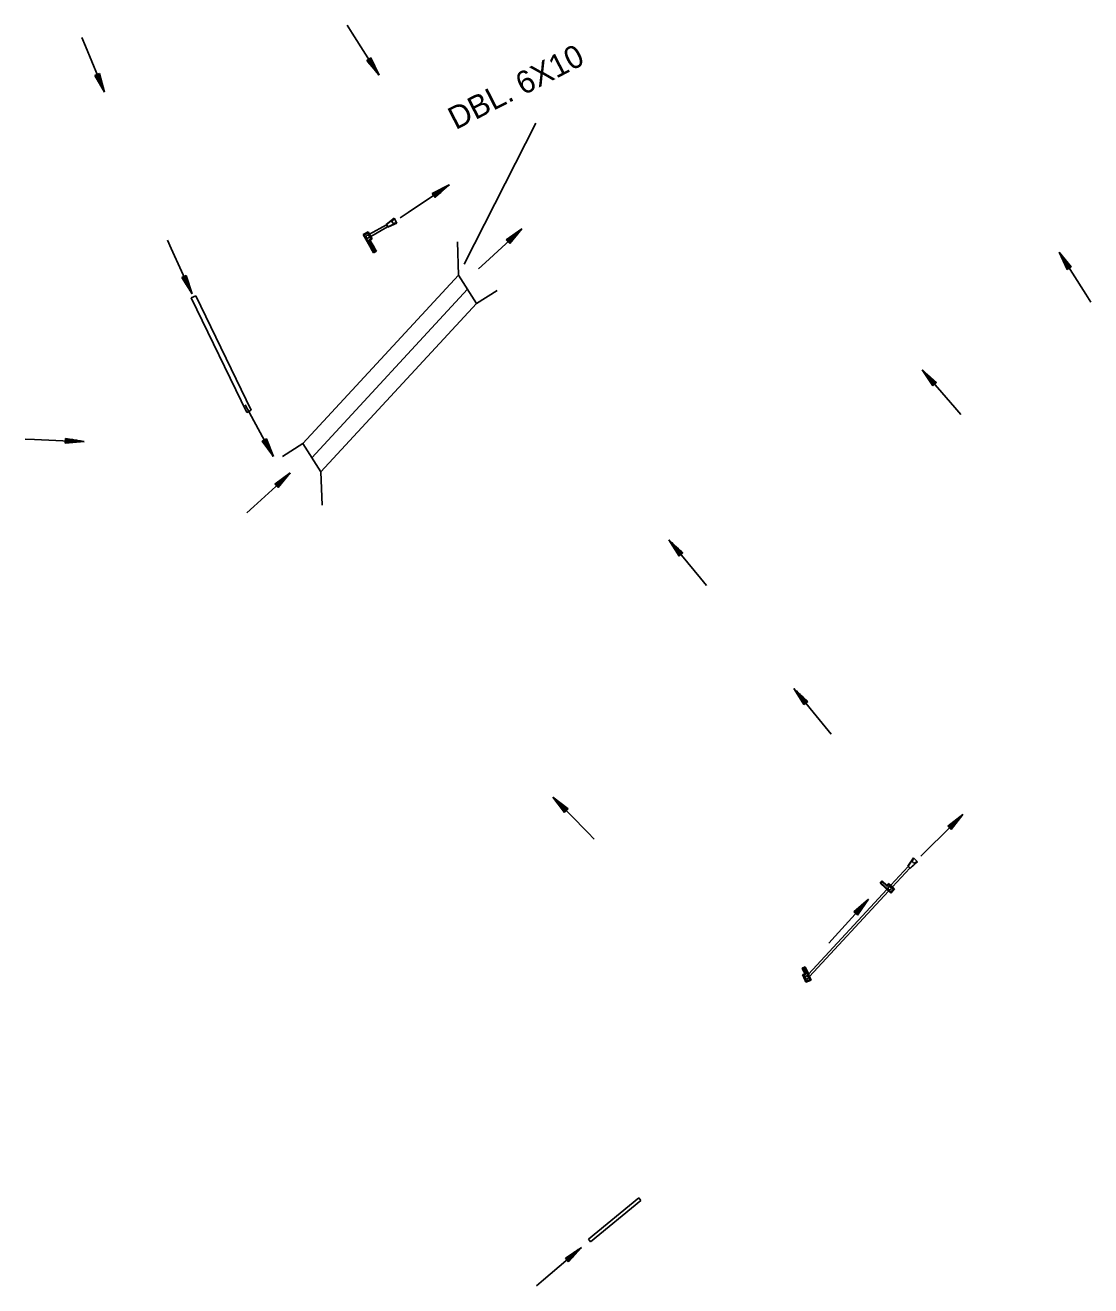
# Model space of a CAD drawing. Extents: x 1308292 to 1312792, y 238563 to 242743.
# Drawn here: x 1312134 to 1312792, y 238563 to 239341 of the extents above; entities that cross this region are included whole.
import ezdxf

# ---------------------------------------------------------------- set-up
doc = ezdxf.new("R2010")
doc.units = 0
for name, color, linetype in [('R_Box Culvert', 7, 'Continuous'), ('R_BRIDGE OLD', 7, 'Continuous'), ('R_Drop Inlet', 7, 'Continuous'), ('R_FES', 7, 'Continuous'), ('R_Flow Arrows', 7, 'Continuous'), ('R_Pipe Culvert', 7, 'Continuous')]:
    doc.layers.add(name, color=color, linetype=linetype)

msp = doc.modelspace()

# ---------------------------------------------------------------- linework, layer by layer
at = {"layer": 'R_Box Culvert'}
for p, q in [((1312401.3, 239187), (1312400.49, 239207.48)), ((1312305.15, 239082.96), (1312401.3, 239187)), ((1312401.3, 239187), (1312412.35, 239169.49)), ((1312310.68, 239074.2), (1312406.82, 239178.24)), ((1312412.35, 239169.49), (1312425.03, 239177.49)), ((1312316.21, 239065.45), (1312412.35, 239169.49)), ((1312292.47, 239074.95), (1312305.15, 239082.96)), ((1312305.15, 239082.96), (1312316.21, 239065.45)), ((1312317.01, 239044.96), (1312316.21, 239065.45))]:
    msp.add_line(p, q, dxfattribs=at)
at = {"layer": 'R_BRIDGE OLD'}
msp.add_line((1312404.65, 239193.81), (1312449.03, 239280.73), dxfattribs=at)
at = {"layer": 'R_Drop Inlet'}
for p, q in [((1312345.43, 239213.74), (1312342.38, 239212.02)), ((1312345.24, 239213.06), (1312343.06, 239211.83)), ((1312347.2, 239209.57), (1312345.9, 239208.84)), ((1312347.89, 239209.39), (1312346.58, 239208.65)), ((1312350.54, 239201.7), (1312348.8, 239200.72)), ((1312349.86, 239201.89), (1312348.99, 239201.4)), ((1312661.44, 238811.39), (1312662.74, 238812.91)), ((1312662.74, 238812.91), (1312665.69, 238810.21)), ((1312661.44, 238811.39), (1312668.08, 238805.31)), ((1312662.13, 238811.43), (1312662.78, 238812.19)), ((1312662.13, 238811.43), (1312668.04, 238806.03)), ((1312662.78, 238812.19), (1312665.74, 238809.49)), ((1312665.69, 238810.21), (1312666.67, 238811.35)), ((1312665.74, 238809.49), (1312666.71, 238810.63)), ((1312666.67, 238811.35), (1312668.1, 238810.04)), ((1312666.71, 238810.63), (1312667.76, 238809.67)), ((1312668.04, 238806.03), (1312669.69, 238807.96)), ((1312668.08, 238805.31), (1312670.39, 238808.01)), ((1312615.15, 238759.74), (1312613.27, 238759.01)), ((1312614.91, 238759.11), (1312613.97, 238758.75)), ((1312615.05, 238755.41), (1312613.65, 238754.87)), ((1312615.72, 238755.14), (1312614.32, 238754.59)), ((1312618.87, 238751.53), (1312615.61, 238750.26)), ((1312618.22, 238751.81), (1312615.89, 238750.91))]:
    msp.add_line(p, q, dxfattribs=at)
for centre in [(1312345.13, 239210.7), (1312667.38, 238808.33), (1312616.3, 238753.21)]:
    msp.add_circle(centre, 1, dxfattribs=at)
for centre, radius, start, end in [((1313743.71, 240000.7), 1608.02, 209.37112, 209.83433), ((1313743.71, 240000.7), 1607.52, 209.38892, 209.81663), ((1313743.71, 240000.7), 1605.02, 209.38887, 209.53166), ((1313743.71, 240000.7), 1604.52, 209.371, 209.54955), ((1313743.71, 240000.7), 1606.52, 209.53156, 209.81688), ((1313743.71, 240000.7), 1606.02, 209.54943, 209.83484), ((1312730.28, 238878), 92.61, 227.54111, 229.13681), ((1312730.28, 238878), 92.11, 227.54111, 229.44615), ((1312438.08, 238668.91), 197, 26.78536, 27.21582), ((1312438.08, 238668.91), 197.5, 26.78536, 27.05463), ((1312545.2, 238722.99), 77.5, 24.50372, 26.78543), ((1312438.08, 238668.91), 198.5, 26.78536, 27.02491), ((1312438.08, 238668.91), 199, 26.78535, 27.15489), ((1312545.2, 238722.99), 78.5, 21.53994, 26.78543), ((1312545.2, 238722.99), 79, 21.17499, 26.78543), ((1312545.2, 238722.99), 75.5, 21.17499, 24.9722), ((1312545.2, 238722.99), 77, 24.89812, 26.78543), ((1312545.2, 238722.99), 76, 21.55194, 24.56949)]:
    msp.add_arc(centre, radius, start, end, dxfattribs=at)
at = {"layer": 'R_FES'}
for p, q in [((1312356.58, 239218.27), (1312361.39, 239222.13)), ((1312356.58, 239218.27), (1312357.52, 239216.6)), ((1312356.82, 239218.19), (1312356.58, 239218.27)), ((1312356.82, 239218.19), (1312361.49, 239221.94)), ((1312356.82, 239218.19), (1312357.57, 239216.85)), ((1312357.52, 239216.6), (1312363.11, 239219.08)), ((1312357.57, 239216.85), (1312363.01, 239219.26)), ((1312360.36, 239220.53), (1312361.39, 239222.13)), ((1312361.49, 239221.94), (1312360.36, 239220.53)), ((1312361.32, 239218.96), (1312363.01, 239219.26)), ((1312363.11, 239219.08), (1312361.32, 239218.96)), ((1312361.39, 239222.13), (1312363.11, 239219.08)), ((1312357.57, 239216.85), (1312357.52, 239216.6)), ((1312678.6, 238821.86), (1312681.98, 238827.02)), ((1312678.6, 238821.86), (1312680.02, 238820.56)), ((1312678.85, 238821.86), (1312678.6, 238821.86)), ((1312678.85, 238821.86), (1312682.13, 238826.87)), ((1312678.85, 238821.86), (1312679.99, 238820.82)), ((1312679.99, 238820.82), (1312684.41, 238824.79)), ((1312679.99, 238820.82), (1312680.02, 238820.56)), ((1312680.02, 238820.56), (1312684.56, 238824.65)), ((1312681.5, 238825.18), (1312681.98, 238827.02)), ((1312682.13, 238826.87), (1312681.5, 238825.18)), ((1312681.98, 238827.02), (1312684.56, 238824.65)), ((1312682.9, 238823.99), (1312684.41, 238824.79)), ((1312684.56, 238824.65), (1312682.9, 238823.99))]:
    msp.add_line(p, q, dxfattribs=at)
for centre, start, end in [((1312361.18, 239219.95), 144.64995, 278.18069), ((1312682.45, 238824.88), 162.7308, 296.26153)]:
    msp.add_arc(centre, 1, start, end, dxfattribs=at)
at = {"layer": 'R_Flow Arrows'}
for p, q in [((1312344.52, 239319.57), (1312347.07, 239321.22)), ((1312344.52, 239319.57), (1312352.17, 239310.53)), ((1312347.07, 239321.22), (1312352.17, 239310.53)), ((1312179.6, 239311.45), (1312176.79, 239310.29)), ((1312179.6, 239311.45), (1312182.68, 239300.01)), ((1312176.79, 239310.29), (1312182.68, 239300.01)), ((1312384.98, 239237.42), (1312395.54, 239242.79)), ((1312386.7, 239234.9), (1312395.54, 239242.79)), ((1312384.98, 239237.42), (1312386.7, 239234.9)), ((1312430.73, 239208.69), (1312440.35, 239215.61)), ((1312432.81, 239206.47), (1312440.35, 239215.61)), ((1312430.73, 239208.69), (1312432.81, 239206.47)), ((1312779.5, 239192.01), (1312771.92, 239201.11)), ((1312776.94, 239190.38), (1312771.92, 239201.11)), ((1312233.13, 239186.73), (1312230.38, 239185.45)), ((1312233.13, 239186.73), (1312236.71, 239175.44)), ((1312776.94, 239190.38), (1312779.5, 239192.01)), ((1312230.38, 239185.45), (1312236.71, 239175.44)), ((1312696.22, 239120.6), (1312687.36, 239128.47)), ((1312693.92, 239118.6), (1312687.36, 239128.47)), ((1312693.92, 239118.6), (1312696.22, 239120.6)), ((1312158.51, 239086.14), (1312158.42, 239083.1)), ((1312158.51, 239086.14), (1312170.21, 239084.24)), ((1312282.64, 239085.96), (1312279.98, 239084.49)), ((1312282.64, 239085.96), (1312287.02, 239074.96)), ((1312158.42, 239083.1), (1312170.21, 239084.24)), ((1312279.98, 239084.49), (1312287.02, 239074.96)), ((1312287.74, 239057.94), (1312297.35, 239064.87)), ((1312289.82, 239055.73), (1312297.35, 239064.87)), ((1312287.74, 239057.94), (1312289.82, 239055.73)), ((1312539.74, 239015.39), (1312531.12, 239023.52)), ((1312537.38, 239013.46), (1312531.12, 239023.52)), ((1312537.38, 239013.46), (1312539.74, 239015.39)), ((1312616.77, 238923.64), (1312608.16, 238931.77)), ((1312614.42, 238921.71), (1312608.16, 238931.77)), ((1312614.42, 238921.71), (1312616.77, 238923.64)), ((1312468.8, 238857.3), (1312459.43, 238864.55)), ((1312466.65, 238855.15), (1312459.43, 238864.55)), ((1312466.65, 238855.15), (1312468.8, 238857.3)), ((1312703.2, 238846.67), (1312712.57, 238853.92)), ((1312705.36, 238844.52), (1312712.57, 238853.92)), ((1312703.2, 238846.67), (1312705.36, 238844.52)), ((1312645.33, 238793.71), (1312654.28, 238801.48)), ((1312647.6, 238791.69), (1312654.28, 238801.48)), ((1312645.33, 238793.71), (1312647.6, 238791.69)), ((1312467.18, 238579.96), (1312477.07, 238586.49)), ((1312467.18, 238579.96), (1312469.17, 238577.66)), ((1312469.17, 238577.66), (1312477.07, 238586.49))]:
    msp.add_line(p, q, dxfattribs=at)
for points in [[(1312332.57, 239341.31), (1312335.63, 239336.42), (1312352.04, 239310.45)], [(1312168.72, 239333.73), (1312170.94, 239328.41), (1312182.68, 239300.01)], [(1312344.77, 239319.74), (1312346.05, 239317.76)], [(1312345.03, 239319.9), (1312347.58, 239315.95)], [(1312345.28, 239320.07), (1312348.66, 239314.85), (1312349.11, 239314.15)], [(1312345.54, 239320.23), (1312348.91, 239315.01), (1312350.65, 239312.34)], [(1312346.05, 239320.56), (1312349.42, 239315.34), (1312351.16, 239312.67)], [(1312346.3, 239320.73), (1312349.68, 239315.51), (1312350.13, 239314.81)], [(1312346.56, 239320.89), (1312349.11, 239316.94)], [(1312346.81, 239321.06), (1312348.09, 239319.08)], [(1312177.91, 239310.75), (1312180.28, 239305.01), (1312181.49, 239302.06)], [(1312178.47, 239310.98), (1312180.85, 239305.24), (1312182.05, 239302.29)], [(1312178.75, 239311.1), (1312181.13, 239305.35), (1312181.44, 239304.58)], [(1312179.03, 239311.22), (1312180.83, 239306.87)], [(1312179.31, 239311.33), (1312180.21, 239309.16)], [(1312177.07, 239310.4), (1312177.96, 239308.23)], [(1312177.35, 239310.52), (1312179.14, 239306.17)], [(1312177.63, 239310.63), (1312180, 239304.89), (1312180.32, 239304.12)], [(1312365.29, 239222.37), (1312370.08, 239225.59), (1312395.62, 239242.67)], [(1312385.5, 239236.66), (1312390.63, 239240.17), (1312391.32, 239240.64)], [(1312385.67, 239236.41), (1312390.8, 239239.92), (1312393.43, 239241.71)], [(1312386.01, 239235.91), (1312391.14, 239239.42), (1312393.77, 239241.21)], [(1312385.15, 239237.16), (1312387.09, 239238.49)], [(1312385.32, 239236.91), (1312389.2, 239239.57)], [(1312386.18, 239235.66), (1312391.31, 239239.17), (1312392, 239239.63)], [(1312386.35, 239235.41), (1312390.23, 239238.06)], [(1312386.53, 239235.16), (1312388.47, 239236.48)], [(1312413.57, 239190.82), (1312417.81, 239194.73), (1312440.45, 239215.5)], [(1312430.94, 239208.46), (1312432.66, 239210.07)], [(1312431.15, 239208.24), (1312434.58, 239211.46)], [(1312431.36, 239208.02), (1312435.9, 239212.27), (1312436.51, 239212.84)], [(1312431.57, 239207.8), (1312436.1, 239212.05), (1312438.43, 239214.22)], [(1312431.98, 239207.35), (1312436.52, 239211.61), (1312438.85, 239213.77)], [(1312432.19, 239207.13), (1312436.73, 239211.38), (1312437.33, 239211.95)], [(1312432.4, 239206.91), (1312435.83, 239210.13)], [(1312221.52, 239208.62), (1312223.91, 239203.37), (1312236.58, 239175.38)], [(1312432.61, 239206.69), (1312434.32, 239208.3)], [(1312791.5, 239170.32), (1312788.4, 239175.18), (1312771.92, 239201.11)], [(1312777.96, 239191.03), (1312774.63, 239196.28), (1312772.93, 239198.97)], [(1312778.48, 239191.36), (1312775.14, 239196.6), (1312773.44, 239199.29)], [(1312777.71, 239190.87), (1312774.37, 239196.12), (1312773.93, 239196.82)], [(1312777.45, 239190.71), (1312774.93, 239194.67)], [(1312778.73, 239191.52), (1312775.4, 239196.77), (1312774.95, 239197.47)], [(1312778.99, 239191.68), (1312776.47, 239195.65)], [(1312232.03, 239186.22), (1312234.65, 239180.58), (1312235.99, 239177.69)], [(1312232.31, 239186.35), (1312234.93, 239180.71), (1312235.28, 239179.95)], [(1312232.58, 239186.47), (1312234.57, 239182.21)], [(1312232.86, 239186.6), (1312233.85, 239184.47)], [(1312777.19, 239190.54), (1312775.93, 239192.53)], [(1312779.25, 239191.85), (1312777.99, 239193.83)], [(1312230.65, 239185.58), (1312231.64, 239183.45)], [(1312230.93, 239185.71), (1312232.91, 239181.44)], [(1312231.2, 239185.83), (1312233.83, 239180.2), (1312234.17, 239179.44)], [(1312231.48, 239185.96), (1312234.1, 239180.32), (1312235.43, 239177.44)], [(1312711.31, 239100.94), (1312707.52, 239105.28), (1312687.36, 239128.47)], [(1312694.84, 239119.4), (1312690.76, 239124.09), (1312688.68, 239126.5)], [(1312695.3, 239119.8), (1312691.22, 239124.49), (1312689.14, 239126.9)], [(1312694.61, 239119.2), (1312690.53, 239123.89), (1312689.98, 239124.53)], [(1312695.53, 239120), (1312691.45, 239124.69), (1312690.9, 239125.32)], [(1312694.38, 239119), (1312691.3, 239122.55)], [(1312694.15, 239118.8), (1312692.61, 239120.58)], [(1312695.76, 239120.2), (1312692.67, 239123.75)], [(1312695.99, 239120.4), (1312694.44, 239122.17)], [(1312269.48, 239106.96), (1312272.25, 239101.9), (1312286.89, 239074.89)], [(1312133.75, 239085.63), (1312139.51, 239085.4), (1312170.2, 239084.09)], [(1312158.48, 239084.92), (1312164.69, 239084.72), (1312167.87, 239084.61)], [(1312158.49, 239085.23), (1312164.7, 239085.03), (1312165.53, 239085)], [(1312158.5, 239085.53), (1312163.19, 239085.38)], [(1312158.51, 239085.83), (1312160.85, 239085.76)], [(1312280.78, 239084.93), (1312283.8, 239079.5), (1312284.2, 239078.77)], [(1312281.04, 239085.08), (1312284.06, 239079.64), (1312285.6, 239076.86)], [(1312281.58, 239085.37), (1312284.6, 239079.94), (1312286.13, 239077.15)], [(1312281.84, 239085.52), (1312284.86, 239080.09), (1312285.26, 239079.36)], [(1312282.11, 239085.67), (1312284.39, 239081.56)], [(1312282.37, 239085.82), (1312283.51, 239083.76)], [(1312158.43, 239083.4), (1312160.78, 239083.33)], [(1312158.44, 239083.71), (1312163.14, 239083.56)], [(1312158.45, 239084.01), (1312164.66, 239083.81), (1312165.49, 239083.78)], [(1312158.46, 239084.31), (1312164.67, 239084.12), (1312167.85, 239084)], [(1312280.25, 239084.64), (1312281.39, 239082.58)], [(1312280.51, 239084.78), (1312282.8, 239080.67)], [(1312270.58, 239040.07), (1312274.81, 239043.99), (1312297.45, 239064.76)], [(1312288.36, 239057.28), (1312292.9, 239061.53), (1312293.51, 239062.1)], [(1312288.57, 239057.06), (1312293.11, 239061.31), (1312295.44, 239063.48)], [(1312288.99, 239056.61), (1312293.52, 239060.86), (1312295.85, 239063.03)], [(1312287.95, 239057.72), (1312289.66, 239059.33)], [(1312288.15, 239057.5), (1312291.58, 239060.72)], [(1312289.19, 239056.39), (1312293.73, 239060.64), (1312294.34, 239061.21)], [(1312289.4, 239056.17), (1312292.83, 239059.38)], [(1312289.61, 239055.95), (1312291.33, 239057.55)], [(1312554.24, 238995.29), (1312550.58, 238999.74), (1312531.12, 239023.52)], [(1312538.32, 239014.23), (1312534.39, 239019.05), (1312532.38, 239021.51)], [(1312538.8, 239014.62), (1312534.86, 239019.43), (1312532.85, 239021.9)], [(1312538.09, 239014.04), (1312534.15, 239018.85), (1312533.63, 239019.5)], [(1312539.03, 239014.81), (1312535.09, 239019.62), (1312534.57, 239020.27)], [(1312537.85, 239013.85), (1312534.88, 239017.49)], [(1312537.62, 239013.66), (1312536.13, 239015.48)], [(1312539.27, 239015), (1312536.29, 239018.64)], [(1312539.5, 239015.2), (1312538.01, 239017.02)], [(1312631.28, 238903.54), (1312627.61, 238907.99), (1312608.16, 238931.77)], [(1312615.36, 238922.48), (1312611.42, 238927.29), (1312609.42, 238929.76)], [(1312615.83, 238922.87), (1312611.9, 238927.68), (1312609.89, 238930.14)], [(1312615.13, 238922.29), (1312611.19, 238927.1), (1312610.66, 238927.75)], [(1312616.07, 238923.06), (1312612.13, 238927.87), (1312611.61, 238928.51)], [(1312614.89, 238922.1), (1312611.91, 238925.73)], [(1312614.66, 238921.9), (1312613.17, 238923.72)], [(1312616.3, 238923.25), (1312613.33, 238926.89)], [(1312616.54, 238923.44), (1312615.05, 238925.26)], [(1312485.03, 238838.54), (1312480.99, 238842.66), (1312459.54, 238864.65)], [(1312467.51, 238856.01), (1312463.12, 238860.42), (1312460.88, 238862.68)], [(1312467.94, 238856.44), (1312463.55, 238860.84), (1312461.31, 238863.1)], [(1312467.29, 238855.8), (1312462.9, 238860.2), (1312462.32, 238860.79)], [(1312468.15, 238856.65), (1312463.77, 238861.06), (1312463.18, 238861.65)], [(1312468.37, 238856.87), (1312465.05, 238860.2)], [(1312467.08, 238855.58), (1312463.76, 238858.91)], [(1312466.86, 238855.37), (1312465.2, 238857.03)], [(1312468.59, 238857.08), (1312466.93, 238858.75)], [(1312686.66, 238828.22), (1312690.76, 238832.28), (1312712.68, 238853.82)], [(1312704.06, 238845.81), (1312708.45, 238850.22), (1312710.7, 238852.46)], [(1312704.49, 238845.38), (1312708.88, 238849.79), (1312711.13, 238852.03)], [(1312703.42, 238846.46), (1312705.08, 238848.12)], [(1312703.63, 238846.24), (1312706.95, 238849.57)], [(1312703.85, 238846.03), (1312708.24, 238850.43), (1312708.83, 238851.02)], [(1312704.71, 238845.17), (1312709.1, 238849.57), (1312709.69, 238850.16)], [(1312704.92, 238844.95), (1312708.24, 238848.28)], [(1312705.14, 238844.74), (1312706.8, 238846.4)], [(1312629.86, 238774.36), (1312633.72, 238778.64), (1312654.39, 238801.38)], [(1312646.01, 238793.11), (1312650.14, 238797.75), (1312650.7, 238798.38)], [(1312646.24, 238792.91), (1312650.37, 238797.55), (1312652.49, 238799.92)], [(1312646.69, 238792.5), (1312650.83, 238797.15), (1312652.95, 238799.52)], [(1312646.92, 238792.3), (1312651.05, 238796.94), (1312651.61, 238797.56)], [(1312645.56, 238793.51), (1312647.12, 238795.27)], [(1312645.78, 238793.31), (1312648.91, 238796.82)], [(1312647.15, 238792.1), (1312650.27, 238795.61)], [(1312647.38, 238791.9), (1312648.94, 238793.65)], [(1312449.3, 238562.81), (1312453.69, 238566.54), (1312477.16, 238586.38)], [(1312467.38, 238579.73), (1312469.16, 238581.27)], [(1312467.58, 238579.5), (1312471.13, 238582.57)], [(1312467.77, 238579.27), (1312472.48, 238583.34), (1312473.11, 238583.88)], [(1312467.97, 238579.04), (1312472.68, 238583.11), (1312475.1, 238585.18)], [(1312468.37, 238578.58), (1312473.08, 238582.64), (1312475.49, 238584.72)], [(1312468.57, 238578.35), (1312473.28, 238582.41), (1312473.91, 238582.96)], [(1312468.77, 238578.12), (1312472.33, 238581.19)], [(1312468.97, 238577.89), (1312470.75, 238579.43)]]:
    msp.add_lwpolyline(points, dxfattribs=at)
at = {"layer": 'R_Pipe Culvert'}
for p, q in [((1312356.68, 239218.09), (1312346.29, 239212.21)), ((1312357.42, 239216.78), (1312347.02, 239210.91)), ((1312236.27, 239172.91), (1312238.97, 239174.22)), ((1312270.61, 239102.2), (1312236.27, 239172.91)), ((1312273.31, 239103.51), (1312238.97, 239174.22)), ((1312270.61, 239102.2), (1312273.31, 239103.51)), ((1312668.01, 238810.12), (1312678.76, 238821.72)), ((1312669.13, 238809.12), (1312679.87, 238820.7)), ((1312617.27, 238755.36), (1312665.63, 238807.55)), ((1312617.92, 238753.86), (1312666.74, 238806.54)), ((1312512.47, 238617.05), (1312481.38, 238591.6)), ((1312513.73, 238615.51), (1312482.65, 238590.05)), ((1312512.47, 238617.05), (1312513.73, 238615.51)), ((1312481.38, 238591.6), (1312482.65, 238590.05))]:
    msp.add_line(p, q, dxfattribs=at)

# ---------------------------------------------------------------- texts
at = {"layer": 'R_BRIDGE OLD'}
msp.add_text('DBL. 6X10', height=14, rotation=27.13195, dxfattribs=at).set_placement((1312399.47, 239276.46))

doc.saveas('drawing.dxf')
